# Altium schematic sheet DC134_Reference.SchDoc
size 431 x 279 mm; Date: Not shown in title block; ApprovedBy: Not shown in title block; CheckedBy: Not shown in title block; Author: Not shown in title block; CompanyName: Not shown in title block; Engineer: Not shown in title block; Organization: Not shown in title block; Address1: Not shown in title block; Address2: Not shown in title block; Address3: Not shown in title block; Address4: Not shown in title block; DocumentNumber: 7; Revision: Use project parameter SCH_Rev; SheetNumber: 7; SheetTotal: 9; PageSetup: Record=PageOptions¦CenterHorizontal=True¦CenterVertical=True¦PrintScale=1.00¦XCorrection=1.00¦YCorrection=1.00¦PrintKind=0¦BorderSize=5000000¦LeftOffset=0¦BottomOffset=0¦Orientation=2¦PaperLength=1000¦PaperWidth=1000¦Scale=100¦PaperSource=15¦PrintQuality=600¦MediaType=1¦DitherType=10¦PaperKind=Letter¦PrintScaleMode=1
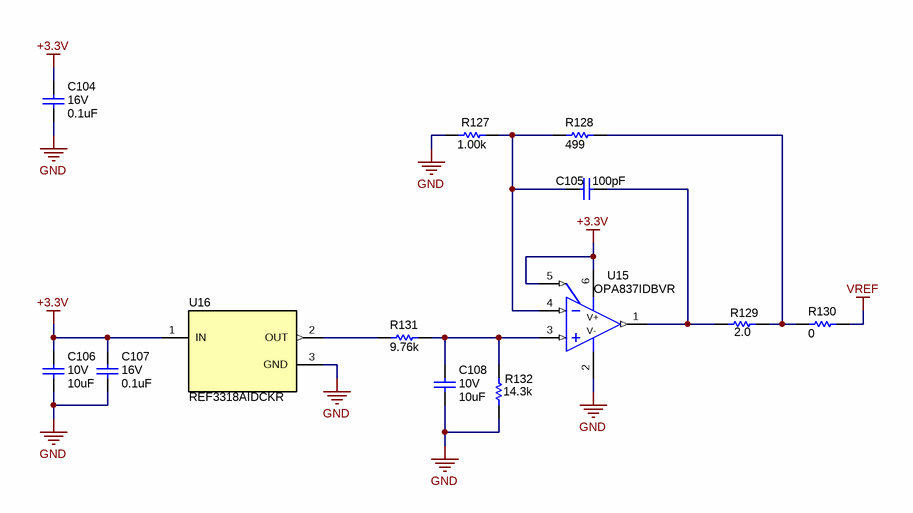
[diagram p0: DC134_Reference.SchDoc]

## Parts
C104  VDC_V: 16V  ValueDisplayed: 0.1uF  [0201L]  (hidden comment: GRM033Z71C104KE14D)
C105  ValueDisplayed: 100pF  [0201_033L]  (hidden comment: GRM033R71E101JA01D)
C106  VDC_V: 10V  ValueDisplayed: 10uF  [0603L]  (hidden comment: GRM188Z71A106MA73D)
C107  VDC_V: 16V  ValueDisplayed: 0.1uF  [0201L]  (hidden comment: GRM033Z71C104KE14D)
C108  VDC_V: 10V  ValueDisplayed: 10uF  [0603L]  (hidden comment: GRM188Z71A106MA73D)
R127  ValueDisplayed: 1.00k  [0201L]  (hidden comment: RC0201FR-071KL)
R128  ValueDisplayed: 499  [0201L]  (hidden comment: RC0201FR-07499RL)
R129  ValueDisplayed: 2.0  [0201L]  (hidden comment: RC0201JR-072RL)
R130  ValueDisplayed: 0  [0201L]  (hidden comment: CRCW02010000Z0ED)
R131  ValueDisplayed: 9.76k  [0201L]  (hidden comment: RC0201FR-079K76L)
R132  ValueDisplayed: 14.3k  [0201L]  (hidden comment: RC0201FR-0714K3L)
U15  OPA837IDBVR  [DBV0006A_N]
U16  REF3318AIDCKR  [DCK0003A_N]

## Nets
+3.3V: C104.1 C106.1 C107.1 U15.5(PD) U15.6(V+) U16.1(IN)
GND: C104.2 C106.2 C107.2 C108.2 R127.1 R132.1 U15.2(V-) U16.3(GND)
VREF: R130.2
NetC105_1: C105.1 R129.1 U15.1(OUT)
NetC105_2: C105.2 R127.2 R128.1 U15.4(IN-)
NetC108_1: C108.1 R131.2 R132.2 U15.3(IN+)
NetR128_2: R128.2 R129.2 R130.1
NetR131_1: R131.1 U16.2(OUT)

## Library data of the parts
C104 C107 = CMP-0064970-1: CAP, CERM, 0.1 uF, 16 V,+/- 10%, X7R, 0201; Manufacturer: MuRata; TaMin_C: -55°C; Polarized: N; SizeAreaWB_mm2: 2.08; Value1: Unknown; U/M: EA; Value: 0.1uF; TaMax_C: 125°C; SizeZ_mm: 0.26; SizeX_mm: 0.6; SizeY_mm: 0.3; Cap_Case: 0201; SizeArea_mm2: 0.18; CompType: Capacitor; Cap_F: 100nF; AEC Category: Q200
C105 = CMP-0009762-1: CAP, CERM, 100 pF, 25 V, +/- 5%, C0G/NP0, 0201; Manufacturer: MuRata; TaMin_C: -55°C; Polarized: N; SizeAreaWB_mm2: 2.08; Value1: Unknown; U/M: EA; Value: 100pF; TaMax_C: 125°C; SizeZ_mm: 0.33; SizeX_mm: 0.6; SizeY_mm: 0.3; Cap_Case: 0201; Value2: 25V; SizeArea_mm2: 0.18; CompType: Capacitor; AEC Category: Q200
C106 C108 = CMP-0007497-5: CAP, CERM, 10 uF, 10 V, +/- 20%, X7R, 0603; Manufacturer: MuRata; TaMin_C: -55°C; Polarized: N; SizeAreaWB_mm2: 4.68; Value1: Unknown; U/M: EA; Value: 10uF; TaMax_C: 125°C; SizeZ_mm: 1; SizeX_mm: 1.6; SizeY_mm: 0.8; Cap_Case: 0603; SizeArea_mm2: 1.28; Cap_F: 10µF; AEC Category: Q200
R127 = CMP-0027453-1: RES, 1.00 k, 1%, 0.05 W, 0201; Manufacturer: Yageo America; Power_W: 50mW; TempCo: 200 ppm/C; Value_Code: 1k00; U/M: EA; Value: 1.00k; EIA_Code: E96; Res_ohm: 1k; SizeX_mm: 0.6; SizeY_mm: 0.3; SizeZ_mm: 0.26; Value2: 0.05W; SizeArea_mm2: 0.18; AEC Qualified: N; VDC_V: 25V; AEC Category: Q200
R128 = CMP-0027731-1: RES, 499, 1%, 0.05 W, 0201; Manufacturer: Yageo America; Power_W: 50mW; TempCo: 200 ppm/C; Value_Code: 499R; U/M: EA; Value: 499; EIA_Code: E96; SizeX_mm: 0.6; SizeY_mm: 0.3; SizeZ_mm: 0.26; Value2: 0.05W; SizeArea_mm2: 0.18; CompType: Resistor; AEC Qualified: N; VDC_V: 25V; AEC Category: Q200
R129 = CMP-0027094-3: RES, 2.0, 5%, 0.05 W, 0201; Manufacturer: Yageo America; Power_W: 50mW; TempCo: 350 ppm/C; Value_Code: 2R00; U/M: EA; Value: 2.0; EIA_Code: E24; Res_ohm: 2; SizeX_mm: 0.6; SizeY_mm: 0.3; SizeZ_mm: 0.26; Value2: 0.05W; SizeArea_mm2: 0.18; CompType: Resistor; AEC Qualified: N; VDC_V: 25V; AEC Category: Q200
R130 = CMP-0027008-4: RES, 0, 5%, 0.05 W, 0201; Manufacturer: Vishay-Dale; Power_W: 50mW; TempCo: ppm/C; Value_Code: 0000; Value: 0; EIA_Code: E24; SizeX_mm: 0.6; SizeY_mm: 0.3; SizeZ_mm: 0.26; Value2: 0.05W; SizeArea_mm2: 0.18; CompType: Resistor; AEC Qualified: N; AEC Category: Q200
R131 = CMP-0027940-1: RES, 9.76 k, 1%, 0.05 W, 0201; Manufacturer: Yageo America; Power_W: 50mW; TempCo: 200 ppm/C; Value_Code: 9k76; U/M: EA; Value: 9.76k; EIA_Code: E96; SizeX_mm: 0.6; SizeY_mm: 0.3; SizeZ_mm: 0.26; Value2: 0.05W; SizeArea_mm2: 0.18; CompType: Resistor; AEC Qualified: N; VDC_V: 25V; AEC Category: Q200
R132 = CMP-0027360-2: RES, 14.3 k, 1%, 0.05 W, 0201; Manufacturer: Yageo America; Power_W: 50mW; TempCo: 200 ppm/C; Value_Code: 14k3; U/M: EA; Value: 14.3k; EIA_Code: E96; SizeX_mm: 0.6; SizeY_mm: 0.3; SizeZ_mm: 0.26; Value2: 0.05W; SizeArea_mm2: 0.18; CompType: Resistor; AEC Qualified: N; VDC_V: 25V; AEC Category: Q200
U15 = CMP-0013237-2: Low Power, Precision, 105MHz, Voltage Feedback Op Amp, DBV0006A (SOT-6); Manufacturer: Texas Instruments; Alternate PartNumber: OPA837IDBVT; SizeX_mm: 2.8; SizeY_mm: 2.9; CompType: IC; SizeZ_mm: 1.45; SizeArea_mm2: 8.12; SizeAreaWB_mm2: 14.82; U/M: EA
U16 = CMP-0032542-1: 30 ppm / degC Drift, 3.9 uA Voltage Reference, -40 to 125 degC, 3-pin SC70 (DCK), Green (RoHS & no Sb/Br); Manufacturer: Texas Instruments; Temp Coeff(Max)(ppm/ degree C): 30; Iout/Iz(Max)(mA): 5; VI(Min)(V): 1.98; SubFamily: Series Voltage Reference; VO(V): 1.8; Rating: Catalog; Temp Coeff(Typ)(ppm/ degree C): 8; VI(Max)(V): 5.5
